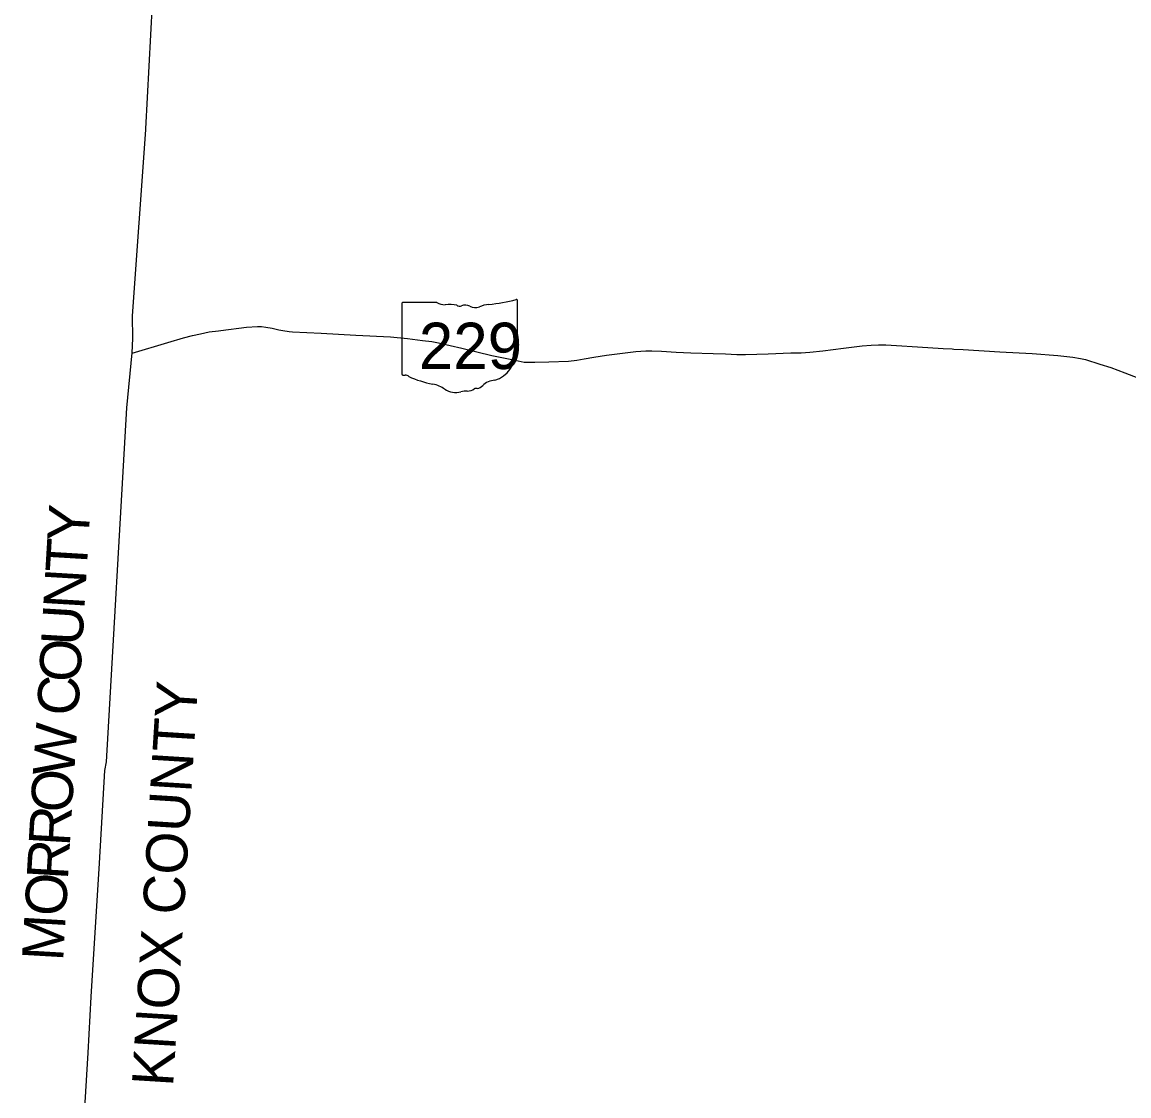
# Model space of a CAD drawing. Extents: x 1851937 to 2123937, y 789467 to 965467.
# Drawn here: x 1926314 to 1953112, y 857229 to 883220 of the extents above; entities that cross this region are included whole.
import ezdxf

# ---------------------------------------------------------------- set-up
doc = ezdxf.new("R2010")
doc.units = 0
for name, color, linetype in [('GM_X_County', 7, 'Continuous'), ('GM_X_County_Text', 7, 'Continuous'), ('GM_X_State_Location', 7, 'Continuous'), ('GM_X_State_Route', 7, 'Continuous'), ('GM_X_State_Shield', 7, 'Continuous')]:
    doc.layers.add(name, color=color, linetype=linetype)

msp = doc.modelspace()

# ---------------------------------------------------------------- linework, layer by layer
at = {"layer": 'GM_X_County'}
msp.add_lwpolyline([(1927783, 856133), (1927916, 858268), (1927987, 859627), (1928187, 862864), (1928313, 865108), (1928357, 865313), (1928848, 873886), (1928976, 875213), (1928998, 875562), (1928986, 876108), (1929311, 880616), (1929312, 880640), (1929553, 885197)], dxfattribs=at)
at = {"layer": 'GM_X_State_Route'}
for points in [[(1928977, 875210), (1929841, 875464), (1930219, 875576), (1930441, 875633), (1930630, 875678), (1930842, 875720), (1931070, 875749)], [(1931070, 875749), (1931122, 875756), (1931751, 875834)], [(1931751, 875834), (1932013, 875856), (1932114, 875854), (1932219, 875840), (1932371, 875811), (1932530, 875774)], [(1932530, 875774), (1932623, 875753), (1932779, 875732), (1932861, 875721), (1933208, 875707), (1933557, 875691), (1934394, 875642), (1935233, 875604), (1935645, 875564), (1936007, 875517), (1936236, 875488), (1936400, 875455), (1936962, 875329), (1937690, 875148)], [(1937690, 875148), (1938051, 875075), (1938323, 875020), (1938467, 874992), (1938725, 874990), (1939067, 874996), (1939542, 875013), (1939747, 875037), (1939923, 875068), (1940160, 875110), (1940467, 875157), (1941178, 875245), (1941419, 875260)], [(1941419, 875260), (1941558, 875263), (1941792, 875256), (1942147, 875235), (1942502, 875219), (1943046, 875197), (1943347, 875189), (1943621, 875173), (1943833, 875177), (1944382, 875191), (1944926, 875214), (1945176, 875214), (1945391, 875231), (1945700, 875266), (1946200, 875325), (1946656, 875385), (1946869, 875398), (1947049, 875411), (1947228, 875409), (1947484, 875395), (1947996, 875362), (1948617, 875322), (1948835, 875311), (1948871, 875304), (1949099, 875295), (1949989, 875238), (1950772, 875196), (1951395, 875153), (1951753, 875112), (1951943, 875081), (1952060, 875053), (1952411, 874938), (1952672, 874856), (1953013, 874727), (1953327, 874607)]]:
    msp.add_lwpolyline(points, dxfattribs=at)
at = {"layer": 'GM_X_State_Shield'}
for p, q in [((1935508, 876405), (1935508, 874704)), ((1936356, 876434), (1935536, 876434)), ((1938310, 875586), (1938310, 876476)), ((1938310, 875586), (1938310, 875586))]:
    msp.add_line(p, q, dxfattribs=at)
for centre, major_axis, start_param, end_param in [((1935540, 876408), (32.5, 0), 1.712693, 3.28349), ((1936552, 876632), (315, 0), 4.042523, 4.731795), ((1936656, 875479), (1130, 0), 1.404758, 1.657858), ((1936913, 876417), (90.8, 0), 3.836095, 5.185415), ((1937046, 876221), (189, 0), 0.950623, 2.079405), ((1937290, 876490), (227, 0), 4.081561, 5.145723), ((1937691, 875914), (598, 0), 1.699011, 2.107814), ((1937312, 878753), (2971, 0), 4.814394, 5.042369), ((1938279, 876480), (31.2, 0), 6.141152, 7.989035), ((1938303, 875521), (48.3, 0), 1.883978, 3.671073), ((1937996, 875408), (290, 0), 5.934695, 6.695948), ((1938277, 875583), (33.4, 0), 5.05454, 6.418171), ((1938422, 875214), (211, 0), 2.387724, 3.262537), ((1937478, 875101), (743, 0), 5.101752, 6.440018), ((1935541, 874700), (32.7, 0), 3.00124, 4.508301), ((1935546, 874874), (250, 0), 4.665946, 4.897461), ((1935597, 874605), (90.1, 0), 0.519207, 1.627899), ((1936734, 876134), (2146, 0), 4.195997, 4.488961), ((1936095, 873939), (671, 0), 0.823519, 1.323587), ((1937276, 874539), (240, 0), 4.937069, 5.64225), ((1937792, 874226), (407, 0), 1.647645, 2.488434), ((1936821, 874597), (426, 0), 4.026481, 4.996735), ((1937067, 874009), (350, 0), 1.495662, 1.94098), ((1937098, 874470), (227, 0), 4.691044, 5.507374), ((1937303, 874305), (63.9, 0), 1.147584, 2.315152)]:
    msp.add_ellipse(centre, major_axis=major_axis, ratio=0.8, start_param=start_param, end_param=end_param, dxfattribs=at)

# ---------------------------------------------------------------- texts
at = {"layer": 'GM_X_County_Text'}
for s, rotation, p in [('Y', 86.589, (1927918, 870621)), ('T', 86.5871, (1927874, 869874)), ('N', 86.589, (1927821, 868991)), ('U', 86.5883, (1927769, 868108)), ('O', 86.5871, (1927716, 867226)), ('C', 86.5833, (1927668, 866413)), ('KNOX COUNTY', 86.448, (1929968, 857440)), ('W', 86.0201, (1927569, 864949)), ('O', 86.5737, (1927516, 864069)), ('R', 86.6605, (1927468, 863257)), ('R', 86.6651, (1927421, 862444)), ('O', 86.6644, (1927370, 861561)), ('M', 86.6639, (1927306, 860476))]:
    msp.add_text(s, height=1000, rotation=rotation, dxfattribs=at).set_placement(p)
at = {"layer": 'GM_X_State_Location'}
for s in ['s', 'r']:
    msp.add_text(s, height=1, dxfattribs=at).set_placement((1936891, 875207))
msp.add_text('229', height=1, rotation=0, dxfattribs=at).set_placement((1936538, 875134))
at = {"layer": 'GM_X_State_Shield'}
msp.add_text('229', height=1120.7, dxfattribs=at).set_placement((1935920, 874824))

doc.saveas('drawing.dxf')
